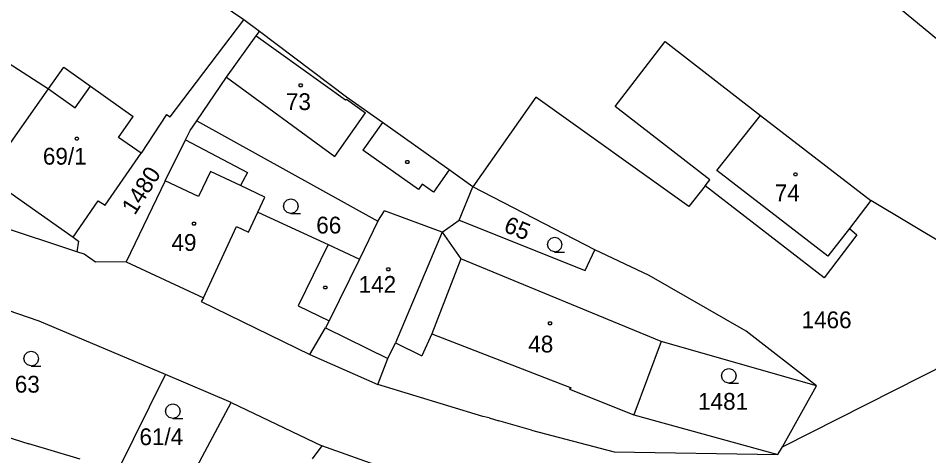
# Model space of a CAD drawing. Extents: x -852001 to -842497, y -1063614 to -1052182.
# Drawn here: x -849216.3 to -849124.2, y -1056197.4 to -1056153.1 of the extents above; entities that cross this region are included whole.
import ezdxf

# ---------------------------------------------------------------- set-up
doc = ezdxf.new("R2010")
doc.units = 0
for name, color, linetype in [('Default', 7, 'Continuous'), ('KN_HRANICE', 7, 'Continuous'), ('KN_KULTURY', 7, 'Continuous'), ('KN_PARCELY', 7, 'Continuous'), ('KN_SLUCKY', 7, 'Continuous')]:
    doc.layers.add(name, color=color, linetype=linetype)

# ---------------------------------------------------------------- blocks, each defined once
blk = doc.blocks.new('304')
at = {"layer": 'Default'}
blk.add_lwpolyline([(0, 0), (-0.38, 0.1), (-0.65, 0.37), (-0.75, 0.74), (-0.65, 1.11), (-0.38, 1.38), (-0.01, 1.48), (0.36, 1.38), (0.63, 1.11), (0.73, 0.73), (0.63, 0.35), (0.36, 0.08), (-0.02, -0.02), (0.98, -0.02)], dxfattribs=at)
blk = doc.blocks.new('402')
at = {"layer": 'Default'}
blk.add_lwpolyline([(0.09, 0.15), (0.18, 0), (0.09, -0.15), (-0.09, -0.15), (-0.18, 0), (-0.09, 0.15), (0.09, 0.15)], dxfattribs=at)

msp = doc.modelspace()

# ---------------------------------------------------------------- linework, layer by layer
at = {"layer": 'KN_HRANICE'}
for p, q in [((-849136.05, -1056144.68), (-849108.72, -1056167.41)), ((-849136.05, -1056144.68), (-849108.72, -1056167.41)), ((-849193.48, -1056153.3), (-849200.44, -1056148.6)), ((-849193.48, -1056153.3), (-849200.44, -1056148.6)), ((-849200.94, -1056163.12), (-849193.48, -1056153.3)), ((-849200.94, -1056163.12), (-849193.48, -1056153.3)), ((-849191.92, -1056154.48), (-849193.48, -1056153.3)), ((-849191.92, -1056154.48), (-849193.48, -1056153.3)), ((-849195.24, -1056159.11), (-849192.23, -1056154.91)), ((-849195.24, -1056159.11), (-849192.23, -1056154.91)), ((-849192.23, -1056154.91), (-849191.92, -1056154.48)), ((-849192.23, -1056154.91), (-849191.92, -1056154.48)), ((-849183.09, -1056161.13), (-849191.92, -1056154.48)), ((-849183.09, -1056161.13), (-849191.92, -1056154.48)), ((-849155.93, -1056162.08), (-849150.85, -1056155.51)), ((-849155.93, -1056162.08), (-849150.85, -1056155.51)), ((-849150.85, -1056155.51), (-849141.2, -1056162.97)), ((-849150.85, -1056155.51), (-849141.2, -1056162.97)), ((-849217.32, -1056157.67), (-849213.24, -1056160.29)), ((-849217.32, -1056157.67), (-849213.24, -1056160.29)), ((-849213.24, -1056160.29), (-849211.69, -1056158.1)), ((-849213.24, -1056160.29), (-849211.69, -1056158.1)), ((-849211.69, -1056158.1), (-849209, -1056160.01)), ((-849211.69, -1056158.1), (-849209, -1056160.01)), ((-849198.23, -1056163.51), (-849195.24, -1056159.11)), ((-849198.23, -1056163.51), (-849195.24, -1056159.11)), ((-849218.67, -1056167.97), (-849213.24, -1056160.29)), ((-849218.67, -1056167.97), (-849213.24, -1056160.29)), ((-849209, -1056160.01), (-849204.67, -1056163.07)), ((-849209, -1056160.01), (-849204.67, -1056163.07)), ((-849179.47, -1056163.69), (-849183.09, -1056161.13)), ((-849179.47, -1056163.69), (-849183.09, -1056161.13)), ((-849163.93, -1056161.11), (-849170.31, -1056170.18)), ((-849163.93, -1056161.11), (-849170.31, -1056170.18)), ((-849148.47, -1056172.18), (-849163.93, -1056161.11)), ((-849148.47, -1056172.18), (-849163.93, -1056161.11)), ((-849146.34, -1056169.48), (-849155.93, -1056162.08)), ((-849146.34, -1056169.48), (-849155.93, -1056162.08)), ((-849206.17, -1056165.19), (-849204.67, -1056163.07)), ((-849206.17, -1056165.19), (-849204.67, -1056163.07)), ((-849201.3, -1056162.87), (-849203.87, -1056166.8)), ((-849201.3, -1056162.87), (-849203.87, -1056166.8)), ((-849201.3, -1056162.87), (-849200.94, -1056163.12)), ((-849201.3, -1056162.87), (-849200.94, -1056163.12)), ((-849198.91, -1056164.5), (-849198.23, -1056163.51)), ((-849198.91, -1056164.5), (-849198.23, -1056163.51)), ((-849198.23, -1056163.51), (-849179.92, -1056173.67)), ((-849198.23, -1056163.51), (-849179.92, -1056173.67)), ((-849141.2, -1056162.97), (-849130.07, -1056171.57)), ((-849141.2, -1056162.97), (-849130.07, -1056171.57)), ((-849172.72, -1056168.47), (-849179.47, -1056163.69)), ((-849172.72, -1056168.47), (-849179.47, -1056163.69)), ((-849203.87, -1056166.8), (-849206.17, -1056165.19)), ((-849203.87, -1056166.8), (-849206.17, -1056165.19)), ((-849199.39, -1056165.45), (-849198.91, -1056164.5)), ((-849199.39, -1056165.45), (-849198.91, -1056164.5)), ((-849201.46, -1056169.6), (-849199.39, -1056165.45)), ((-849201.46, -1056169.6), (-849199.39, -1056165.45)), ((-849199.39, -1056165.45), (-849193.13, -1056168.74)), ((-849199.39, -1056165.45), (-849193.13, -1056168.74)), ((-849207.51, -1056172.06), (-849203.87, -1056166.8)), ((-849207.51, -1056172.06), (-849203.87, -1056166.8)), ((-849193.13, -1056168.74), (-849193.84, -1056170.06)), ((-849193.13, -1056168.74), (-849193.84, -1056170.06)), ((-849170.31, -1056170.18), (-849172.72, -1056168.47)), ((-849170.31, -1056170.18), (-849172.72, -1056168.47)), ((-849201.46, -1056169.6), (-849205.39, -1056177.77)), ((-849201.46, -1056169.6), (-849205.39, -1056177.77)), ((-849146.81, -1056170.1), (-849146.34, -1056169.48)), ((-849146.81, -1056170.1), (-849146.34, -1056169.48)), ((-849217.17, -1056170.75), (-849210.75, -1056175.28)), ((-849217.17, -1056170.75), (-849210.75, -1056175.28)), ((-849191.35, -1056171.24), (-849193.84, -1056170.06)), ((-849191.35, -1056171.24), (-849193.84, -1056170.06)), ((-849171.71, -1056173.55), (-849170.31, -1056170.18)), ((-849171.71, -1056173.55), (-849170.31, -1056170.18)), ((-849157.98, -1056176.57), (-849170.31, -1056170.18)), ((-849157.98, -1056176.57), (-849170.31, -1056170.18)), ((-849146.81, -1056170.1), (-849148.47, -1056172.18)), ((-849146.81, -1056170.1), (-849148.47, -1056172.18)), ((-849134.79, -1056179.4), (-849146.81, -1056170.1)), ((-849134.79, -1056179.4), (-849146.81, -1056170.1)), ((-849210.75, -1056175.28), (-849208.24, -1056171.61)), ((-849210.75, -1056175.28), (-849208.24, -1056171.61)), ((-849208.24, -1056171.61), (-849207.51, -1056172.06)), ((-849208.24, -1056171.61), (-849207.51, -1056172.06)), ((-849192.07, -1056172.77), (-849191.35, -1056171.24)), ((-849192.07, -1056172.77), (-849191.35, -1056171.24)), ((-849130.07, -1056171.57), (-849132.2, -1056174.42)), ((-849130.07, -1056171.57), (-849132.2, -1056174.42)), ((-849122.32, -1056176.18), (-849130.07, -1056171.57)), ((-849122.32, -1056176.18), (-849130.07, -1056171.57)), ((-849210.39, -1056176.75), (-849224.5, -1056172.08)), ((-849210.39, -1056176.75), (-849224.5, -1056172.08)), ((-849179.92, -1056173.67), (-849179.25, -1056172.62)), ((-849179.92, -1056173.67), (-849179.25, -1056172.62)), ((-849173.41, -1056174.79), (-849179.25, -1056172.62)), ((-849173.41, -1056174.79), (-849179.25, -1056172.62)), ((-849192.07, -1056172.77), (-849184.95, -1056176.04)), ((-849192.07, -1056172.77), (-849184.95, -1056176.04)), ((-849179.92, -1056173.67), (-849181.8, -1056177.49)), ((-849179.92, -1056173.67), (-849181.8, -1056177.49)), ((-849173.41, -1056174.79), (-849171.71, -1056173.55)), ((-849173.41, -1056174.79), (-849171.71, -1056173.55)), ((-849171.71, -1056173.55), (-849158.94, -1056178.64)), ((-849171.71, -1056173.55), (-849158.94, -1056178.64)), ((-849132.2, -1056174.42), (-849131.47, -1056175.04)), ((-849132.2, -1056174.42), (-849131.47, -1056175.04)), ((-849210.75, -1056175.28), (-849210.2, -1056175.67)), ((-849210.75, -1056175.28), (-849210.2, -1056175.67)), ((-849173.41, -1056174.79), (-849171.52, -1056177.46)), ((-849173.41, -1056174.79), (-849171.52, -1056177.46)), ((-849131.47, -1056175.04), (-849134.79, -1056179.4)), ((-849131.47, -1056175.04), (-849134.79, -1056179.4)), ((-849210.2, -1056175.67), (-849210.39, -1056176.75)), ((-849210.2, -1056175.67), (-849210.39, -1056176.75)), ((-849184.95, -1056176.04), (-849181.8, -1056177.49)), ((-849184.95, -1056176.04), (-849181.8, -1056177.49)), ((-849209.65, -1056177), (-849210.39, -1056176.75)), ((-849209.65, -1056177), (-849210.39, -1056176.75)), ((-849208.48, -1056177.82), (-849209.65, -1056177)), ((-849208.48, -1056177.82), (-849209.65, -1056177)), ((-849158.94, -1056178.64), (-849157.98, -1056176.57)), ((-849158.94, -1056178.64), (-849157.98, -1056176.57)), ((-849152.47, -1056179.17), (-849157.98, -1056176.57)), ((-849152.47, -1056179.17), (-849157.98, -1056176.57)), ((-849205.39, -1056177.77), (-849208.48, -1056177.82)), ((-849205.39, -1056177.77), (-849208.48, -1056177.82)), ((-849205.39, -1056177.77), (-849197.58, -1056181.42)), ((-849205.39, -1056177.77), (-849197.58, -1056181.42)), ((-849181.8, -1056177.49), (-849184.87, -1056183.74)), ((-849181.8, -1056177.49), (-849184.87, -1056183.74)), ((-849171.52, -1056177.46), (-849174.47, -1056185.05)), ((-849171.52, -1056177.46), (-849174.47, -1056185.05)), ((-849142.67, -1056184.79), (-849152.47, -1056179.17)), ((-849142.67, -1056184.79), (-849152.47, -1056179.17)), ((-849214.19, -1056183.77), (-849219.9, -1056181.81)), ((-849214.19, -1056183.77), (-849219.9, -1056181.81)), ((-849197.58, -1056181.42), (-849197.79, -1056181.8)), ((-849197.58, -1056181.42), (-849197.79, -1056181.8)), ((-849197.79, -1056181.8), (-849186.8, -1056187.14)), ((-849197.79, -1056181.8), (-849186.8, -1056187.14)), ((-849139, -1056196.47), (-849111.09, -1056182.39)), ((-849139, -1056196.47), (-849111.09, -1056182.39)), ((-849201.43, -1056189.17), (-849214.19, -1056183.77)), ((-849201.43, -1056189.17), (-849214.19, -1056183.77)), ((-849184.87, -1056183.74), (-849185.22, -1056184.46)), ((-849184.87, -1056183.74), (-849185.22, -1056184.46)), ((-849186.8, -1056187.14), (-849185.22, -1056184.46)), ((-849186.8, -1056187.14), (-849185.22, -1056184.46)), ((-849174.47, -1056185.05), (-849175.47, -1056187.27)), ((-849174.47, -1056185.05), (-849175.47, -1056187.27)), ((-849135.54, -1056190.32), (-849142.67, -1056184.79)), ((-849135.54, -1056190.32), (-849142.67, -1056184.79)), ((-849178.93, -1056187.55), (-849178.15, -1056185.97)), ((-849178.93, -1056187.55), (-849178.15, -1056185.97)), ((-849178.15, -1056185.97), (-849175.47, -1056187.27)), ((-849178.15, -1056185.97), (-849175.47, -1056187.27)), ((-849151.28, -1056185.84), (-849154.04, -1056193.23)), ((-849151.28, -1056185.84), (-849154.04, -1056193.23)), ((-849135.54, -1056190.32), (-849151.28, -1056185.84)), ((-849135.54, -1056190.32), (-849151.28, -1056185.84)), ((-849186.8, -1056187.14), (-849179.92, -1056190.19)), ((-849186.8, -1056187.14), (-849179.92, -1056190.19)), ((-849179.92, -1056190.19), (-849178.93, -1056187.55)), ((-849179.92, -1056190.19), (-849178.93, -1056187.55)), ((-849206.24, -1056198.9), (-849201.43, -1056189.17)), ((-849206.24, -1056198.9), (-849201.43, -1056189.17)), ((-849194.76, -1056191.99), (-849201.43, -1056189.17)), ((-849194.76, -1056191.99), (-849201.43, -1056189.17)), ((-849169.32, -1056193.41), (-849179.92, -1056190.19)), ((-849169.32, -1056193.41), (-849179.92, -1056190.19)), ((-849139, -1056196.47), (-849135.54, -1056190.32)), ((-849139, -1056196.47), (-849135.54, -1056190.32)), ((-849199.24, -1056200.34), (-849194.76, -1056191.99)), ((-849199.24, -1056200.34), (-849194.76, -1056191.99)), ((-849194.76, -1056191.99), (-849185.6, -1056196.38)), ((-849194.76, -1056191.99), (-849185.6, -1056196.38)), ((-849168.67, -1056193.56), (-849169.32, -1056193.41)), ((-849168.67, -1056193.56), (-849169.32, -1056193.41)), ((-849168.67, -1056193.56), (-849167.69, -1056193.85)), ((-849168.67, -1056193.56), (-849167.69, -1056193.85)), ((-849164.4, -1056194.78), (-849167.69, -1056193.85)), ((-849164.4, -1056194.78), (-849167.69, -1056193.85)), ((-849154.04, -1056193.23), (-849139.45, -1056197.27)), ((-849154.04, -1056193.23), (-849139.45, -1056197.27)), ((-849219.79, -1056194.73), (-849215.25, -1056196.17)), ((-849219.79, -1056194.73), (-849215.25, -1056196.17)), ((-849164.4, -1056194.78), (-849156.01, -1056196.98)), ((-849164.4, -1056194.78), (-849156.01, -1056196.98)), ((-849210.06, -1056197.72), (-849215.25, -1056196.17)), ((-849210.06, -1056197.72), (-849215.25, -1056196.17)), ((-849185.6, -1056196.38), (-849186.57, -1056197.69)), ((-849185.6, -1056196.38), (-849186.57, -1056197.69)), ((-849169.42, -1056202.11), (-849185.6, -1056196.38)), ((-849169.42, -1056202.11), (-849185.6, -1056196.38)), ((-849139.45, -1056197.27), (-849139, -1056196.47)), ((-849139.45, -1056197.27), (-849139, -1056196.47)), ((-849156.01, -1056196.98), (-849139.45, -1056197.27)), ((-849156.01, -1056196.98), (-849139.45, -1056197.27))]:
    msp.add_line(p, q, dxfattribs=at)
at = {"layer": 'KN_SLUCKY'}
for p, q in [((-849192.23, -1056154.91), (-849183.2, -1056161.41)), ((-849192.23, -1056154.91), (-849183.2, -1056161.41)), ((-849195.24, -1056159.11), (-849184.29, -1056167.12)), ((-849195.24, -1056159.11), (-849184.29, -1056167.12)), ((-849213.24, -1056160.29), (-849210.54, -1056162.19)), ((-849213.24, -1056160.29), (-849210.54, -1056162.19)), ((-849210.54, -1056162.19), (-849209, -1056160.01)), ((-849210.54, -1056162.19), (-849209, -1056160.01)), ((-849183.2, -1056161.41), (-849183.11, -1056161.33)), ((-849183.2, -1056161.41), (-849183.11, -1056161.33)), ((-849183.11, -1056161.33), (-849181.19, -1056162.7)), ((-849183.11, -1056161.33), (-849181.19, -1056162.7)), ((-849184.29, -1056167.12), (-849181.19, -1056162.7)), ((-849184.29, -1056167.12), (-849181.19, -1056162.7)), ((-849145.62, -1056168.53), (-849141.2, -1056162.97)), ((-849145.62, -1056168.53), (-849141.2, -1056162.97)), ((-849179.47, -1056163.69), (-849181.44, -1056166.48)), ((-849179.47, -1056163.69), (-849181.44, -1056166.48)), ((-849175.83, -1056170.45), (-849181.44, -1056166.48)), ((-849175.83, -1056170.45), (-849181.44, -1056166.48)), ((-849196.86, -1056168.63), (-849198.06, -1056171.16)), ((-849196.86, -1056168.63), (-849198.06, -1056171.16)), ((-849193.84, -1056170.06), (-849196.86, -1056168.63)), ((-849193.84, -1056170.06), (-849196.86, -1056168.63)), ((-849172.72, -1056168.47), (-849174.31, -1056170.73)), ((-849172.72, -1056168.47), (-849174.31, -1056170.73)), ((-849134.39, -1056177.2), (-849145.62, -1056168.53)), ((-849134.39, -1056177.2), (-849145.62, -1056168.53)), ((-849198.06, -1056171.16), (-849201.46, -1056169.6)), ((-849198.06, -1056171.16), (-849201.46, -1056169.6)), ((-849175.46, -1056169.92), (-849175.83, -1056170.45)), ((-849175.46, -1056169.92), (-849175.83, -1056170.45)), ((-849174.31, -1056170.73), (-849175.46, -1056169.92)), ((-849174.31, -1056170.73), (-849175.46, -1056169.92)), ((-849193.01, -1056174.76), (-849192.07, -1056172.77)), ((-849193.01, -1056174.76), (-849192.07, -1056172.77)), ((-849197.58, -1056181.42), (-849194.23, -1056174.19)), ((-849197.58, -1056181.42), (-849194.23, -1056174.19)), ((-849194.23, -1056174.19), (-849193.01, -1056174.76)), ((-849194.23, -1056174.19), (-849193.01, -1056174.76)), ((-849132.2, -1056174.42), (-849134.39, -1056177.2)), ((-849132.2, -1056174.42), (-849134.39, -1056177.2)), ((-849173.41, -1056174.79), (-849178.15, -1056185.97)), ((-849173.41, -1056174.79), (-849178.15, -1056185.97)), ((-849184.95, -1056176.04), (-849187.98, -1056182.21)), ((-849184.95, -1056176.04), (-849187.98, -1056182.21)), ((-849151.28, -1056185.84), (-849171.52, -1056177.46)), ((-849151.28, -1056185.84), (-849171.52, -1056177.46)), ((-849187.98, -1056182.21), (-849184.87, -1056183.74)), ((-849187.98, -1056182.21), (-849184.87, -1056183.74)), ((-849185.22, -1056184.46), (-849178.93, -1056187.55)), ((-849185.22, -1056184.46), (-849178.93, -1056187.55)), ((-849174.47, -1056185.05), (-849160.38, -1056190.53)), ((-849174.47, -1056185.05), (-849160.38, -1056190.53)), ((-849160.38, -1056190.53), (-849160.53, -1056190.66)), ((-849160.38, -1056190.53), (-849160.53, -1056190.66)), ((-849160.53, -1056190.66), (-849154.04, -1056193.23)), ((-849160.53, -1056190.66), (-849154.04, -1056193.23))]:
    msp.add_line(p, q, dxfattribs=at)

# ---------------------------------------------------------------- block references
at = {"layer": 'KN_KULTURY'}
for name, p in [('402', (-849187.74, -1056159.93)), ('402', (-849187.74, -1056159.93)), ('402', (-849210.38, -1056165.31)), ('402', (-849210.38, -1056165.31)), ('402', (-849176.95, -1056167.68)), ('402', (-849176.95, -1056167.68)), ('402', (-849137.67, -1056168.92)), ('402', (-849137.67, -1056168.92)), ('304', (-849188.72, -1056172.88)), ('304', (-849188.72, -1056172.88)), ('402', (-849198.52, -1056173.91)), ('402', (-849198.52, -1056173.91)), ('304', (-849162.03, -1056176.77)), ('304', (-849162.03, -1056176.77)), ('402', (-849178.86, -1056178.52)), ('402', (-849178.86, -1056178.52)), ('402', (-849185.25, -1056180.37)), ('402', (-849185.25, -1056180.37)), ('402', (-849162.52, -1056183.98)), ('402', (-849162.52, -1056183.98)), ('304', (-849215, -1056188.3)), ('304', (-849215, -1056188.3)), ('304', (-849144.41, -1056190.03)), ('304', (-849144.41, -1056190.03)), ('304', (-849200.65, -1056193.61)), ('304', (-849200.65, -1056193.61))]:
    msp.add_blockref(name, p, dxfattribs=at)

# ---------------------------------------------------------------- texts
at = {"layer": 'KN_PARCELY'}
for s, p in [('73', (-849189.229, -1056162.43)), ('73', (-849189.229, -1056162.43)), ('69/1', (-849213.817, -1056167.95)), ('69/1', (-849213.817, -1056167.95)), ('74', (-849139.77, -1056171.65)), ('74', (-849139.77, -1056171.65)), ('66', (-849186.16, -1056174.91)), ('66', (-849186.16, -1056174.91)), ('49', (-849200.809, -1056176.67)), ('49', (-849200.809, -1056176.67)), ('142', (-849181.87, -1056180.91)), ('142', (-849181.87, -1056180.91)), ('1466', (-849137.06, -1056184.49)), ('1466', (-849137.06, -1056184.49)), ('48', (-849164.709, -1056186.94)), ('48', (-849164.709, -1056186.94)), ('63', (-849216.66, -1056191)), ('63', (-849216.66, -1056191)), ('1481', (-849147.527, -1056192.73)), ('1481', (-849147.527, -1056192.73)), ('61/4', (-849204.05, -1056196.31)), ('61/4', (-849204.05, -1056196.31))]:
    msp.add_text(s, height=1.7, dxfattribs=at).set_placement(p)
for s, rotation, p in [('1480', 57.582, (-849204.521, -1056173.136)), ('1480', 57.582, (-849204.521, -1056173.136)), ('65', 337.931, (-849167.298, -1056174.686)), ('65', 337.931, (-849167.298, -1056174.686))]:
    msp.add_text(s, height=1.7, rotation=rotation, dxfattribs=at).set_placement(p)

doc.saveas('drawing.dxf')
